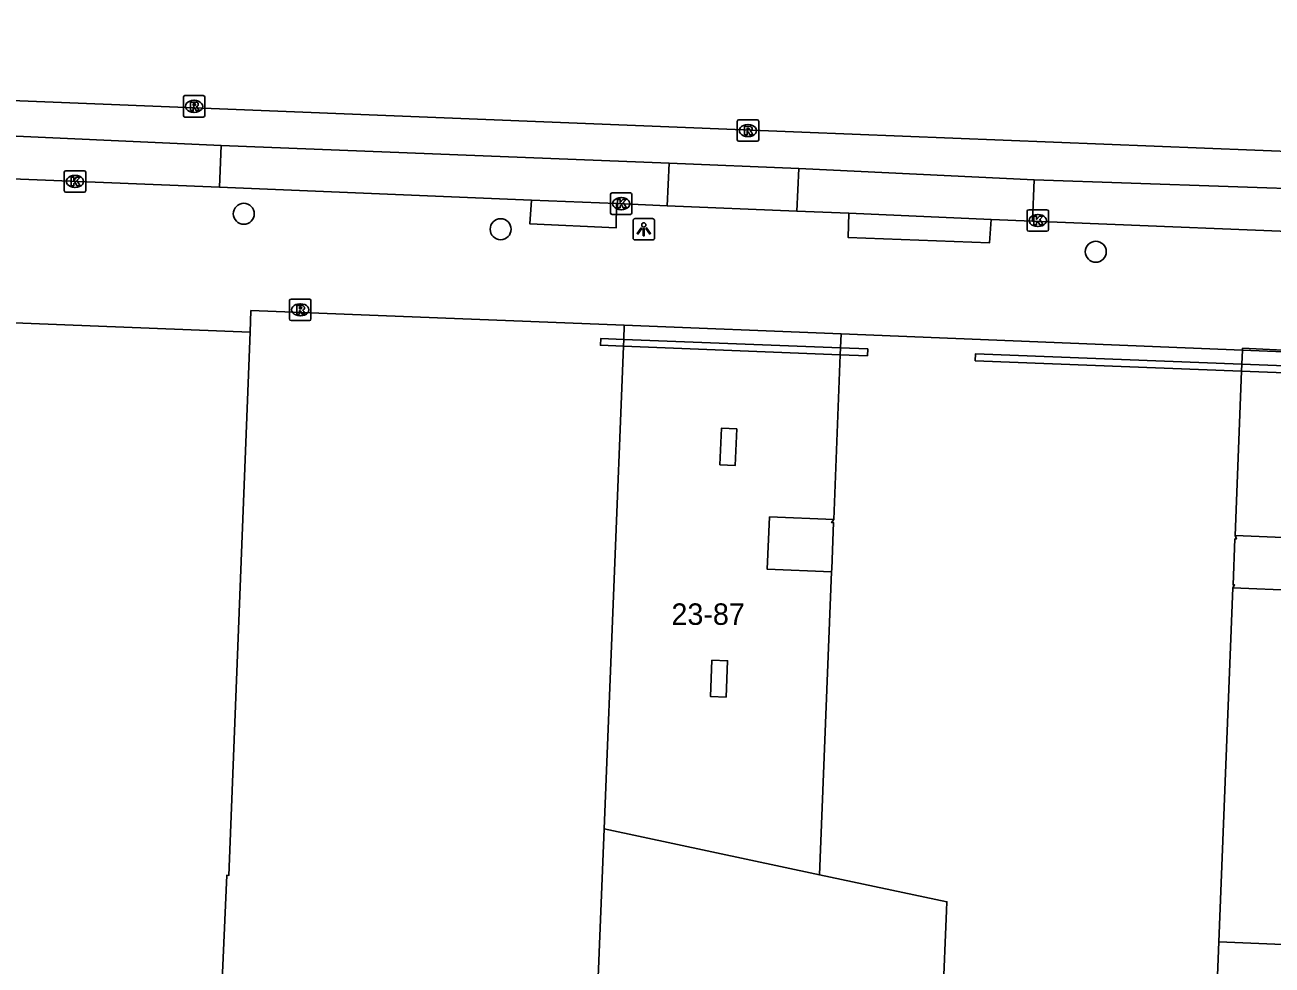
# Model space of a CAD drawing. Extents: x 160891 to 161384, y 386490 to 386907.
# Drawn here: x 161211.9 to 161270, y 386856.8 to 386900.6 of the extents above; entities that cross this region are included whole.
import ezdxf

# ---------------------------------------------------------------- set-up
doc = ezdxf.new("R2010")
doc.units = 0
for name, color, linetype in [('IMGEO_Boom', 7, 'Continuous'), ('IMGEO_Hek', 7, 'Continuous'), ('IMGEO_Kolk', 7, 'Continuous'), ('IMGEO_Lichtpunt', 7, 'Continuous'), ('IMGEO_Muur', 7, 'Continuous'), ('IMGEO_Pand', 7, 'Continuous'), ('IMGEO_Pand_nummerreeks', 7, 'Continuous'), ('IMGEO_Pand_overbouw', 7, 'Continuous'), ('IMGEO_Rijbaan_lokaal_gesloten', 7, 'Continuous'), ('IMGEO_Rioolput', 7, 'Continuous'), ('IMGEO_Voetpad_open', 7, 'Continuous')]:
    doc.layers.add(name, color=color, linetype=linetype)

msp = doc.modelspace()

# ---------------------------------------------------------------- linework, layer by layer
at = {"layer": 'IMGEO_Boom'}
for centre in [(161222.068, 386891.761), (161234.033, 386891.042), (161261.759, 386889.993)]:
    msp.add_circle(centre, 0.489, dxfattribs=at)
at = {"layer": 'IMGEO_Hek'}
for points in [[(161249.544, 386877.375), (161249.453, 386877.378), (161249.549, 386877.514)], [(161268.249, 386876.768), (161268.307, 386876.617), (161268.243, 386876.619)], [(161249.452, 386875.087), (161249.458, 386875.226)], [(161268.157, 386874.473), (161268.226, 386874.47), (161268.151, 386874.333)]]:
    msp.add_lwpolyline(points, dxfattribs=at)
at = {"layer": 'IMGEO_Kolk'}
for p, q in [((161213.701, 386892.843), (161213.701, 386893.695)), ((161213.776, 386893.769), (161214.628, 386893.769)), ((161214.189, 386893.549), (161214.214, 386893.549)), ((161214.702, 386893.695), (161214.702, 386892.843)), ((161214.212, 386892.989), (161214.187, 386892.989)), ((161214.628, 386892.769), (161213.776, 386892.769)), ((161239.15, 386891.807), (161239.15, 386892.659)), ((161239.225, 386892.733), (161240.077, 386892.733)), ((161239.638, 386892.513), (161239.663, 386892.513)), ((161240.151, 386892.659), (161240.151, 386891.807)), ((161240.077, 386891.733), (161239.225, 386891.733)), ((161239.661, 386891.953), (161239.636, 386891.953)), ((161258.557, 386891.024), (161258.557, 386891.876)), ((161258.632, 386891.95), (161259.484, 386891.95)), ((161259.045, 386891.73), (161259.07, 386891.73)), ((161259.558, 386891.876), (161259.558, 386891.024)), ((161259.068, 386891.17), (161259.043, 386891.17)), ((161259.484, 386890.95), (161258.632, 386890.95))]:
    msp.add_line(p, q, dxfattribs=at)
for points in [[(161213.701, 386892.843), (161213.701, 386893.695)], [(161213.776, 386893.769), (161214.628, 386893.769)], [(161214.022, 386893.469), (161214.145, 386893.469), (161214.145, 386893.318), (161214.275, 386893.469), (161214.439, 386893.469), (161214.293, 386893.318), (161214.446, 386893.069), (161214.294, 386893.069), (161214.209, 386893.233), (161214.145, 386893.166), (161214.145, 386893.069), (161214.022, 386893.069), (161214.022, 386893.469)], [(161214.702, 386893.695), (161214.702, 386892.843)], [(161214.628, 386892.769), (161213.776, 386892.769)], [(161239.15, 386891.807), (161239.15, 386892.659)], [(161239.225, 386892.733), (161240.077, 386892.733)], [(161239.471, 386892.433), (161239.594, 386892.433), (161239.594, 386892.282), (161239.724, 386892.433), (161239.888, 386892.433), (161239.742, 386892.282), (161239.895, 386892.033), (161239.743, 386892.033), (161239.658, 386892.197), (161239.594, 386892.13), (161239.594, 386892.033), (161239.471, 386892.033), (161239.471, 386892.433)], [(161240.151, 386892.659), (161240.151, 386891.807)], [(161240.077, 386891.733), (161239.225, 386891.733)], [(161258.557, 386891.024), (161258.557, 386891.876)], [(161258.632, 386891.95), (161259.484, 386891.95)], [(161259.558, 386891.876), (161259.558, 386891.024)], [(161258.878, 386891.65), (161259.001, 386891.65), (161259.001, 386891.499), (161259.131, 386891.65), (161259.295, 386891.65), (161259.149, 386891.499), (161259.302, 386891.25), (161259.15, 386891.25), (161259.065, 386891.414), (161259.001, 386891.347), (161259.001, 386891.25), (161258.878, 386891.25), (161258.878, 386891.65)], [(161259.484, 386890.95), (161258.632, 386890.95)]]:
    msp.add_lwpolyline(points, dxfattribs=at)
for centre, start, end in [((161213.778, 386893.693), 91.55205, 178.44795), ((161213.778, 386893.693), 91.55205, 178.44795), ((161214.626, 386893.693), 1.55205, 88.44795), ((161214.626, 386893.693), 1.55205, 88.44795), ((161213.778, 386892.845), 181.55205, 268.44795), ((161213.778, 386892.845), 181.55205, 268.44795), ((161214.626, 386892.845), 271.55205, 358.44795), ((161214.626, 386892.845), 271.55205, 358.44795), ((161239.227, 386892.657), 91.55205, 178.44795), ((161239.227, 386892.657), 91.55205, 178.44795), ((161240.075, 386892.657), 1.55205, 88.44795), ((161240.075, 386892.657), 1.55205, 88.44795), ((161239.227, 386891.809), 181.55205, 268.44795), ((161239.227, 386891.809), 181.55205, 268.44795), ((161240.075, 386891.809), 271.55205, 358.44795), ((161240.075, 386891.809), 271.55205, 358.44795), ((161258.634, 386891.874), 91.55205, 178.44795), ((161258.634, 386891.874), 91.55205, 178.44795), ((161259.482, 386891.874), 1.55205, 88.44795), ((161259.482, 386891.874), 1.55205, 88.44795), ((161258.634, 386891.026), 181.55205, 268.44795), ((161258.634, 386891.026), 181.55205, 268.44795), ((161259.482, 386891.026), 271.55205, 358.44795), ((161259.482, 386891.026), 271.55205, 358.44795)]:
    msp.add_arc(centre, 0.0765, start, end, dxfattribs=at)
for centre, major_axis, ratio, start_param, end_param in [((161214.188, 386893.269), (-0.387, 0.002), 0.722429, 4.712389, 7.853982), ((161214.213, 386893.269), (-0.39, 0.002), 0.717154, 1.570796, 4.712389), ((161239.637, 386892.233), (-0.387, 0.002), 0.722429, 4.712389, 7.853982), ((161239.662, 386892.233), (-0.39, 0.002), 0.717154, 1.570796, 4.712389), ((161259.044, 386891.45), (-0.387, 0.002), 0.722429, 4.712389, 7.853982), ((161259.069, 386891.45), (-0.39, 0.002), 0.717154, 1.570796, 4.712389)]:
    msp.add_ellipse(centre, major_axis=major_axis, ratio=ratio, start_param=start_param, end_param=end_param, dxfattribs=at)
at = {"layer": 'IMGEO_Lichtpunt'}
for p, q in [((161240.204, 386891.445), (161240.204, 386890.638)), ((161240.204, 386891.445), (161240.204, 386890.638)), ((161241.106, 386891.54), (161240.298, 386891.54)), ((161241.106, 386891.54), (161240.298, 386891.54)), ((161241.2, 386890.638), (161241.2, 386891.445)), ((161241.2, 386890.638), (161241.2, 386891.445)), ((161240.298, 386890.544), (161241.106, 386890.544)), ((161240.298, 386890.544), (161241.106, 386890.544))]:
    msp.add_line(p, q, dxfattribs=at)
for points in [[(161240.578, 386891.109), (161240.617, 386891.081), (161240.429, 386890.819), (161240.391, 386890.846), (161240.578, 386891.109)], [(161240.79, 386891.081), (161240.828, 386891.108), (161241.015, 386890.846), (161240.976, 386890.818), (161240.79, 386891.081)], [(161240.68, 386891.061), (161240.727, 386891.061), (161240.727, 386890.739), (161240.68, 386890.739), (161240.68, 386891.061)]]:
    msp.add_lwpolyline(points, dxfattribs=at)
msp.add_circle((161240.703, 386891.243), 0.0994, dxfattribs=at)
for centre, start, end in [((161240.298, 386891.445), 90, 180), ((161240.298, 386891.445), 90, 180), ((161241.106, 386891.445), 0, 90), ((161241.106, 386891.445), 0, 90), ((161240.298, 386890.638), 180, 270), ((161240.298, 386890.638), 180, 270), ((161241.106, 386890.638), 270, 0), ((161241.106, 386890.638), 270, 360)]:
    msp.add_arc(centre, 0.0946, start, end, dxfattribs=at)
at = {"layer": 'IMGEO_Muur'}
for points in [[(161239.754, 386885.591), (161238.684, 386885.633), (161238.696, 386885.947), (161239.766, 386885.905)], [(161239.766, 386885.905), (161239.754, 386885.591)], [(161239.766, 386885.905), (161249.87, 386885.511)], [(161249.857, 386885.197), (161239.754, 386885.591)], [(161249.857, 386885.197), (161249.87, 386885.511)], [(161249.87, 386885.511), (161251.132, 386885.462), (161251.119, 386885.148), (161249.857, 386885.197)], [(161268.554, 386884.432), (161256.14, 386884.914), (161256.153, 386885.234), (161268.567, 386884.752)], [(161268.567, 386884.752), (161268.554, 386884.432)], [(161268.567, 386884.752), (161278.663, 386884.36)], [(161278.65, 386884.04), (161268.554, 386884.432)]]:
    msp.add_lwpolyline(points, dxfattribs=at)
at = {"layer": 'IMGEO_Pand'}
for points in [[(161210.581, 386886.706), (161222.369, 386886.248)], [(161222.369, 386886.248), (161221.375, 386860.939), (161221.275, 386860.943), (161221.078, 386856.403), (161221.066, 386856.099), (161221.271, 386856.091), (161221.965, 386856.062), (161221.919, 386854.943), (161229.279, 386854.644), (161238.505, 386854.269), (161238.86, 386863.105), (161248.886, 386860.967), (161254.82, 386859.706), (161254.804, 386859.3), (161254.641, 386855.168), (161257.979, 386855.044), (161267.366, 386854.695), (161267.493, 386857.839), (161277.574, 386857.417), (161277.385, 386852.718), (161283.395, 386852.488)], [(161244.242, 386880.066), (161244.315, 386881.769), (161245.032, 386881.738), (161244.959, 386880.036), (161244.242, 386880.066)], [(161249.458, 386875.226), (161249.452, 386875.087), (161246.455, 386875.203), (161246.559, 386877.641), (161249.549, 386877.514), (161249.453, 386877.378), (161249.544, 386877.375), (161249.458, 386875.226)], [(161268.243, 386876.619), (161268.307, 386876.617), (161268.249, 386876.768), (161271.239, 386876.642), (161271.137, 386874.214), (161268.151, 386874.333), (161268.226, 386874.47), (161268.157, 386874.473), (161268.243, 386876.619)], [(161244.542, 386869.236), (161243.815, 386869.264), (161243.879, 386870.962), (161244.606, 386870.935), (161244.542, 386869.236)]]:
    msp.add_lwpolyline(points, dxfattribs=at)
at = {"layer": 'IMGEO_Pand_overbouw'}
for points in [[(161249.896, 386886.171), (161239.793, 386886.567), (161239.766, 386885.905), (161239.754, 386885.591), (161238.86, 386863.105), (161248.886, 386860.967), (161249.452, 386875.087), (161246.455, 386875.203), (161246.559, 386877.641), (161249.549, 386877.514), (161249.857, 386885.197), (161249.87, 386885.511)], [(161268.597, 386885.494), (161268.594, 386885.414), (161268.567, 386884.752), (161268.554, 386884.432), (161268.249, 386876.768), (161271.239, 386876.642), (161271.137, 386874.214), (161268.151, 386874.333), (161267.493, 386857.839), (161277.574, 386857.417), (161278.65, 386884.04), (161278.663, 386884.36), (161278.689, 386885.003)]]:
    msp.add_lwpolyline(points, close=True, dxfattribs=at)
at = {"layer": 'IMGEO_Rijbaan_lokaal_gesloten'}
for points in [[(161123.263, 386900.56), (161248.069, 386895.57), (161278.544, 386894.358), (161279.11, 386894.349)], [(161221.008, 386894.938), (161209.056, 386895.484)], [(161221.008, 386894.938), (161220.937, 386892.996)], [(161241.882, 386894.123), (161221.008, 386894.938)], [(161241.794, 386892.138), (161241.882, 386894.123)], [(161247.927, 386893.867), (161241.882, 386894.123)], [(161247.927, 386893.867), (161247.831, 386891.89)], [(161258.887, 386893.342), (161247.927, 386893.867)], [(161220.937, 386892.996), (161235.468, 386892.398)], [(161258.81, 386891.423), (161258.887, 386893.342)], [(161277.593, 386892.717), (161276.971, 386892.717), (161258.887, 386893.342)], [(161235.468, 386892.398), (161239.425, 386892.236)], [(161239.425, 386892.236), (161241.794, 386892.138)], [(161247.831, 386891.89), (161250.255, 386891.79)], [(161250.255, 386891.79), (161256.885, 386891.501)], [(161256.885, 386891.501), (161258.81, 386891.423)]]:
    msp.add_lwpolyline(points, dxfattribs=at)
at = {"layer": 'IMGEO_Rioolput'}
for p, q in [((161219.251, 386896.342), (161219.251, 386897.194)), ((161219.326, 386897.268), (161220.178, 386897.268)), ((161219.739, 386897.048), (161219.764, 386897.048)), ((161220.252, 386897.194), (161220.252, 386896.342)), ((161219.762, 386896.488), (161219.737, 386896.488)), ((161220.178, 386896.268), (161219.326, 386896.268)), ((161245.054, 386895.212), (161245.054, 386896.064)), ((161245.129, 386896.138), (161245.981, 386896.138)), ((161245.542, 386895.918), (161245.567, 386895.918)), ((161246.055, 386896.064), (161246.055, 386895.212)), ((161245.565, 386895.358), (161245.54, 386895.358)), ((161245.981, 386895.138), (161245.129, 386895.138)), ((161224.196, 386886.862), (161224.196, 386887.714)), ((161224.271, 386887.788), (161225.123, 386887.788)), ((161225.197, 386887.714), (161225.197, 386886.862)), ((161224.707, 386887.008), (161224.682, 386887.008)), ((161224.684, 386887.568), (161224.709, 386887.568)), ((161225.123, 386886.788), (161224.271, 386886.788))]:
    msp.add_line(p, q, dxfattribs=at)
for points in [[(161219.251, 386896.342), (161219.251, 386897.194)], [(161219.326, 386897.268), (161220.178, 386897.268)], [(161219.84, 386896.966), (161219.588, 386896.968), (161219.588, 386896.568)], [(161219.766, 386896.887), (161219.712, 386896.887), (161219.712, 386896.806)], [(161220.252, 386897.194), (161220.252, 386896.342)], [(161219.588, 386896.568), (161219.712, 386896.568), (161219.712, 386896.73), (161219.723, 386896.73)], [(161219.712, 386896.806), (161219.764, 386896.806)], [(161219.77, 386896.701), (161219.841, 386896.568), (161219.981, 386896.568), (161219.916, 386896.694)], [(161220.178, 386896.268), (161219.326, 386896.268)], [(161245.054, 386895.212), (161245.054, 386896.064)], [(161245.129, 386896.138), (161245.981, 386896.138)], [(161245.643, 386895.836), (161245.391, 386895.838), (161245.391, 386895.438)], [(161245.569, 386895.757), (161245.515, 386895.757), (161245.515, 386895.676)], [(161246.055, 386896.064), (161246.055, 386895.212)], [(161245.391, 386895.438), (161245.515, 386895.438), (161245.515, 386895.6), (161245.526, 386895.6)], [(161245.515, 386895.676), (161245.567, 386895.676)], [(161245.573, 386895.571), (161245.644, 386895.438), (161245.784, 386895.438), (161245.719, 386895.564)], [(161245.981, 386895.138), (161245.129, 386895.138)], [(161224.196, 386886.862), (161224.196, 386887.714)], [(161224.271, 386887.788), (161225.123, 386887.788)], [(161225.197, 386887.714), (161225.197, 386886.862)], [(161224.785, 386887.486), (161224.533, 386887.488), (161224.533, 386887.088)], [(161224.533, 386887.088), (161224.657, 386887.088), (161224.657, 386887.25), (161224.668, 386887.25)], [(161224.711, 386887.407), (161224.657, 386887.407), (161224.657, 386887.326)], [(161224.657, 386887.326), (161224.709, 386887.326)], [(161224.715, 386887.221), (161224.786, 386887.088), (161224.926, 386887.088), (161224.861, 386887.214)], [(161225.123, 386886.788), (161224.271, 386886.788)]]:
    msp.add_lwpolyline(points, dxfattribs=at)
for centre, radius, start, end in [((161219.328, 386897.192), 0.0765, 91.55205, 178.44795), ((161219.328, 386897.192), 0.0765, 91.55205, 178.44795), ((161219.772, 386896.791), 0.0964, 77.00612, 93.18647), ((161219.786, 386896.848), 0.0378, 276.66336, 79.67722), ((161219.839, 386896.856), 0.109, 350.36119, 89.41601), ((161220.176, 386897.192), 0.0765, 1.55205, 88.44795), ((161220.176, 386897.192), 0.0765, 1.55205, 88.44795), ((161219.328, 386896.344), 0.0765, 181.55205, 268.44795), ((161219.328, 386896.344), 0.0765, 181.55205, 268.44795), ((161219.722, 386896.677), 0.0533, 26.02933, 88.69889), ((161219.748, 386896.995), 0.19, 274.7715, 282.96867), ((161219.837, 386896.856), 0.112, 277.58423, 350.98172), ((161219.821, 386896.641), 0.108, 29.51342, 73.79051), ((161220.176, 386896.344), 0.0765, 271.55205, 358.44795), ((161220.176, 386896.344), 0.0765, 271.55205, 358.44795), ((161245.131, 386896.062), 0.0765, 91.55205, 178.44795), ((161245.131, 386896.062), 0.0765, 91.55205, 178.44795), ((161245.575, 386895.661), 0.0964, 77.00612, 93.18647), ((161245.589, 386895.718), 0.0378, 276.66336, 79.67722), ((161245.642, 386895.726), 0.109, 350.36119, 89.41601), ((161245.979, 386896.062), 0.0765, 1.55205, 88.44795), ((161245.979, 386896.062), 0.0765, 1.55205, 88.44795), ((161245.131, 386895.214), 0.0765, 181.55205, 268.44795), ((161245.131, 386895.214), 0.0765, 181.55205, 268.44795), ((161245.525, 386895.547), 0.0533, 26.02933, 88.69889), ((161245.551, 386895.865), 0.19, 274.7715, 282.96867), ((161245.64, 386895.726), 0.112, 277.58423, 350.98172), ((161245.624, 386895.511), 0.108, 29.51342, 73.79051), ((161245.979, 386895.214), 0.0765, 271.55205, 358.44795), ((161245.979, 386895.214), 0.0765, 271.55205, 358.44795), ((161224.273, 386887.712), 0.0765, 91.55205, 178.44795), ((161224.273, 386887.712), 0.0765, 91.55205, 178.44795), ((161225.121, 386887.712), 0.0765, 1.55205, 88.44795), ((161225.121, 386887.712), 0.0765, 1.55205, 88.44795), ((161224.667, 386887.197), 0.0533, 26.02933, 88.69889), ((161224.693, 386887.515), 0.19, 274.7715, 282.96867), ((161224.717, 386887.311), 0.0964, 77.00612, 93.18647), ((161224.731, 386887.368), 0.0378, 276.66336, 79.67722), ((161224.784, 386887.376), 0.109, 350.36119, 89.41601), ((161224.782, 386887.376), 0.112, 277.58423, 350.98172), ((161224.766, 386887.161), 0.108, 29.51342, 73.79051), ((161224.273, 386886.864), 0.0765, 181.55205, 268.44795), ((161224.273, 386886.864), 0.0765, 181.55205, 268.44795), ((161225.121, 386886.864), 0.0765, 271.55205, 358.44795), ((161225.121, 386886.864), 0.0765, 271.55205, 358.44795)]:
    msp.add_arc(centre, radius, start, end, dxfattribs=at)
for centre, major_axis, ratio, start_param, end_param in [((161219.738, 386896.768), (-0.387, 0.002), 0.722429, 4.712389, 7.853982), ((161219.763, 386896.768), (-0.39, 0.002), 0.717154, 1.570796, 4.712389), ((161245.541, 386895.638), (-0.387, 0.002), 0.722429, 4.712389, 7.853982), ((161245.566, 386895.638), (-0.39, 0.002), 0.717154, 1.570796, 4.712389), ((161224.683, 386887.288), (-0.387, 0.002), 0.722429, 4.712389, 7.853982), ((161224.708, 386887.288), (-0.39, 0.002), 0.717154, 1.570796, 4.712389)]:
    msp.add_ellipse(centre, major_axis=major_axis, ratio=ratio, start_param=start_param, end_param=end_param, dxfattribs=at)
at = {"layer": 'IMGEO_Voetpad_open'}
for points in [[(161208.945, 386893.49), (161220.937, 386892.996)], [(161239.425, 386892.236), (161239.41, 386891.107), (161235.397, 386891.29), (161235.468, 386892.398)], [(161241.794, 386892.138), (161247.831, 386891.89)], [(161256.885, 386891.501), (161256.805, 386890.402), (161250.217, 386890.662), (161250.255, 386891.79)], [(161258.81, 386891.423), (161274.2, 386890.804)], [(161222.369, 386886.248), (161222.396, 386887.248), (161239.793, 386886.567), (161249.896, 386886.171), (161268.594, 386885.414), (161278.689, 386885.003)]]:
    msp.add_lwpolyline(points, dxfattribs=at)

# ---------------------------------------------------------------- texts
at = {"layer": 'IMGEO_Pand_nummerreeks'}
msp.add_text('23-87', height=1, dxfattribs=at).set_placement((161241.989, 386872.609))

doc.saveas('drawing.dxf')
